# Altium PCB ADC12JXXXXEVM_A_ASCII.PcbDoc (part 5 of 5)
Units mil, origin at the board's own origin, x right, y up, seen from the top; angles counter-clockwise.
Board outline 5739 x 2680 mil, 10 copper layers (Top Layer L1, Gnd-Plane - L2, Signals - L3, Gnd-Plane - L4, Pwr Plane - L5, Signals - L6, Gnd-Plane - L7, Signals - L8, Gnd-Plane - L9, Bottom Layer - L10), stack 57.8 mil thick; 582 components, 343 nets, 1924 pads, 1318 vias.
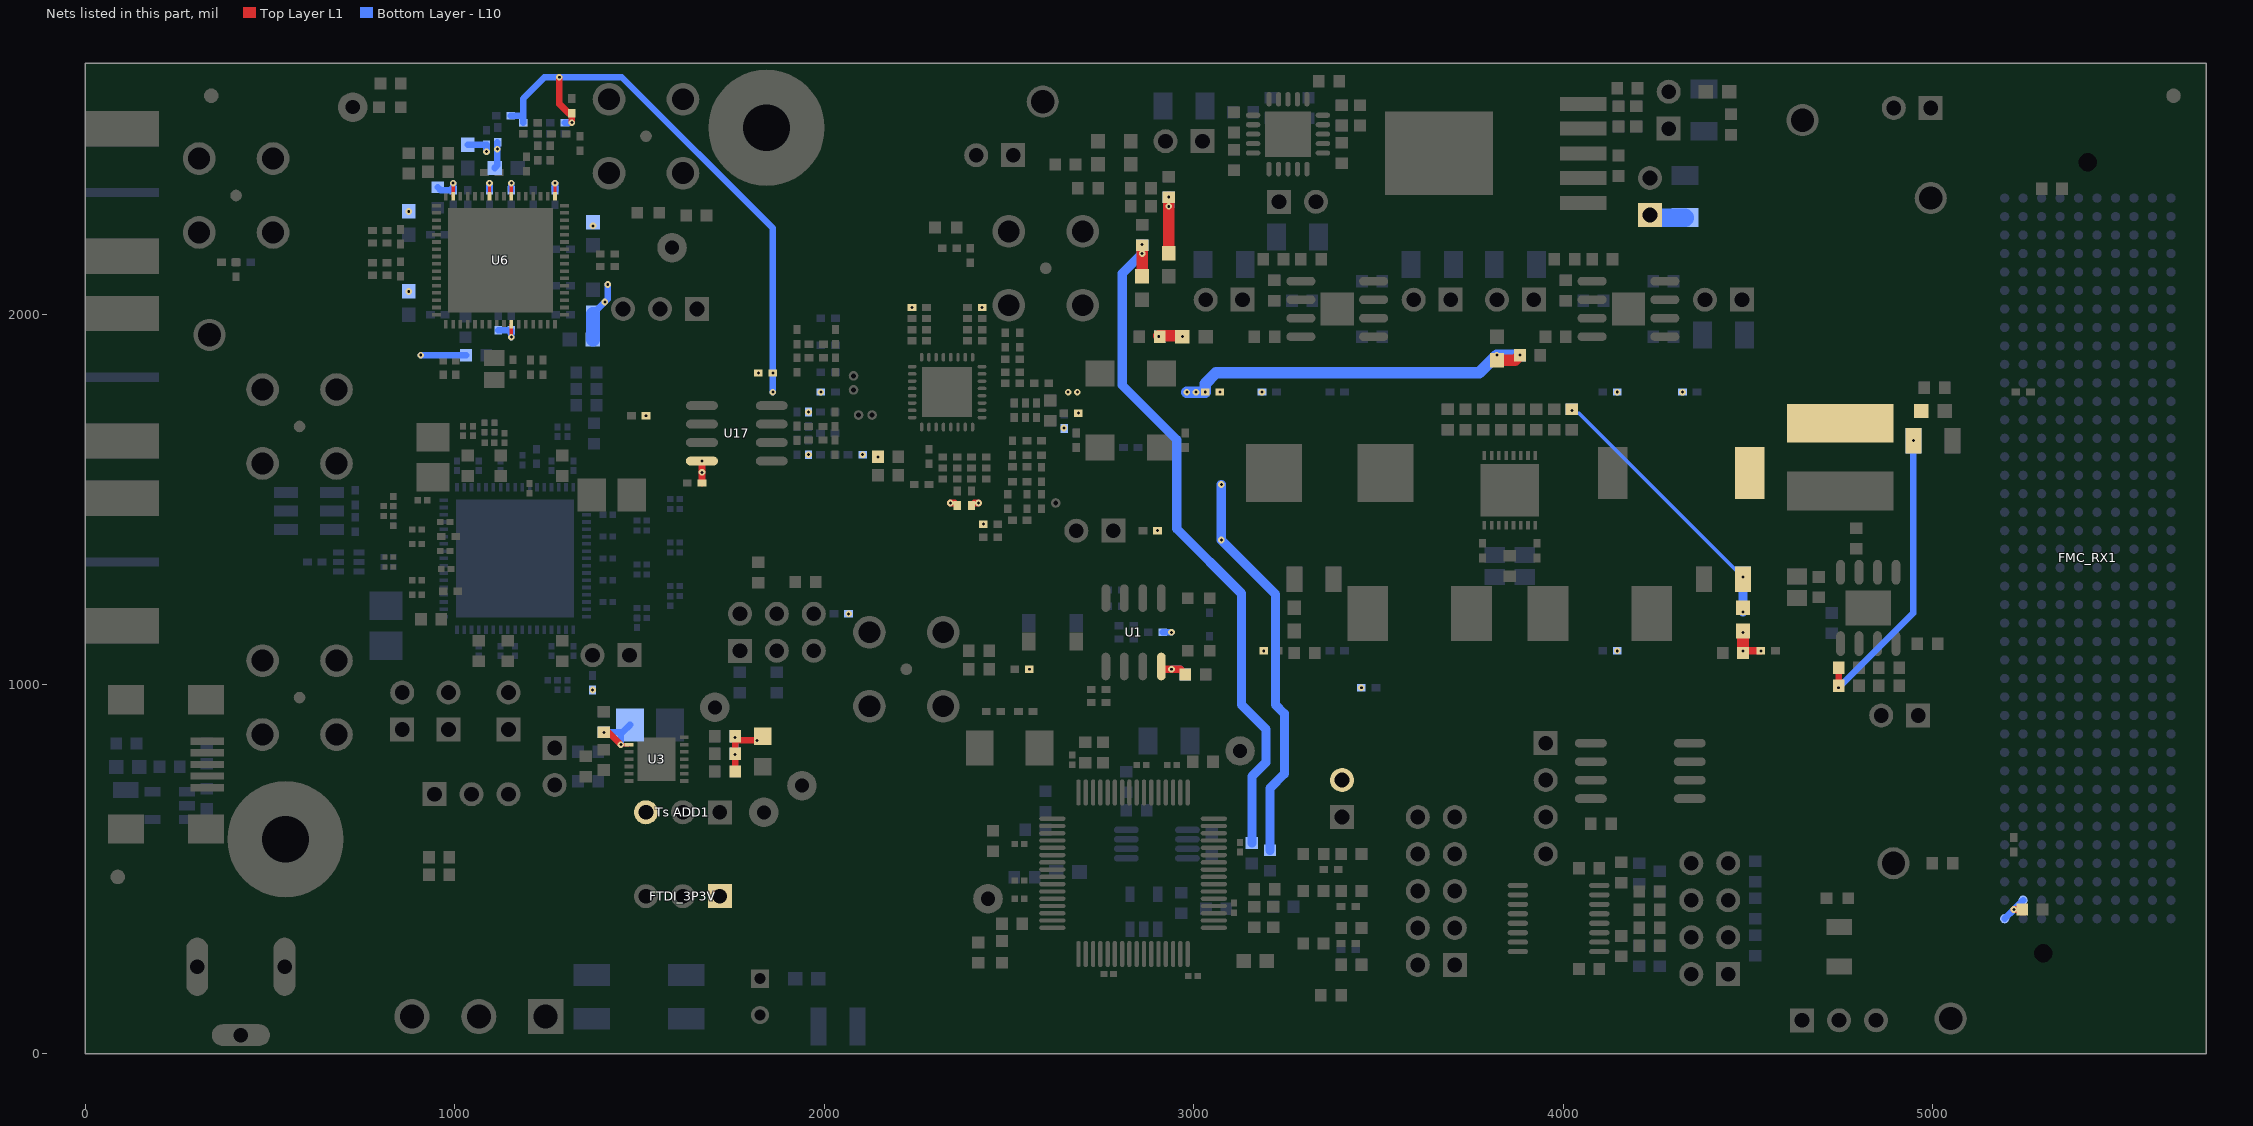
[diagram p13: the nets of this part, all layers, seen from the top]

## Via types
v1: diameter 18, hole 8, Top Layer L1 to Bottom Layer - L10, tented both sides, 1098 vias
v2: diameter 19.68, hole 7.87, Top Layer L1 to Bottom Layer - L10, 99 vias
v3: diameter 18, hole 8, Top Layer L1 to Bottom Layer - L10, tented bottom, 58 vias
v4: diameter 18, hole 8, Top Layer L1 to Bottom Layer - L10, tented top, 48 vias
v5: diameter 25.98, hole 12.99, Top Layer L1 to Bottom Layer - L10, tented top, 8 vias
v6: diameter 19.68, hole 7.87, Top Layer L1 to Bottom Layer - L10, tented top, 5 vias
v7: diameter 126, hole 106, Top Layer L1 to Bottom Layer - L10, tented top, 2 vias

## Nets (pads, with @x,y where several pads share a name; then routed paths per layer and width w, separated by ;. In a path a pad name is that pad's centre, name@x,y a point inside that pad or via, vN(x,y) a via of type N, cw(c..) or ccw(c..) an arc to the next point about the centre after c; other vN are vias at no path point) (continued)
VIO_2P25: 1V9INT.1 C199.1 C203.1 C222.1 C223.1 C226.1 C227.1 L20.2 R95.1 | length 258.5
  Top Layer L1 w19.5: v1(4486.15,1090) v1(4534.31,1090)
  Top Layer L1 w31.5: v1(4486.15,1090) L20.2@4486.15,1143.5
  Bottom Layer - L10 w24: C203.1@4486.15,1084 v1@4486.15,1143.5
  Bottom Layer - L10 w51: 1V9INT.1@4234,2269.07 4241.09,2261.98 R95.1@4328.44,2261.98
  other v1: 4145.69,1090 4486.15,1140 4145.69,1790 4322.32,1790
VIO_2P25V: C174.2 C180.1 C181.1 L11.1 L20.1 R81.1 | length 745.3
  Bottom Layer - L10 w10: R81.1@4023,1743.56 4033.56,1733 4042,1733 4470,1305 4470,1299.15 C181.1@4486.15,1283
  Bottom Layer - L10 w24: v1@4486.15,1195 C181.1@4486.15,1283
  other v1: 4486.15,1195 4486.15,1290 4023,1740
VIO_3P3V: "Ts ADD1.3" C24.1 C25.1 C27.1 C95.1 C96.1 C115.1 C125.1 C153.1 C163.1 C215.1 C216.1 C217.1 C218.1 C219.2 C220.1 C224.2 FTDI_3P3V.1 J3.2 L9.2 R1.2 R14.2 R15.2 R16.2 R31.2 R32.2 TEMP.1 U1.8 U3.2 | length 651.2
  Top Layer L1 w9: v1(1449.28,836.13) U3.2@1471.47,836.13
  Top Layer L1 w18: v1(1403.28,869.44) 1415.96,869.44 v1(1449.28,836.13) ; R16.2@1758.84,763.41 v1(1758.84,809.41) 1758.84,847.47 v1(1818.28,847.47)
  Top Layer L1 w19.5: U1.8@2912,1040 2962.93,1040 C125.1@2976.93,1026
  Top Layer L1 w30: C153.1@2905,1942.56 2966.45,1942.56 v1(2969.01,1940)
  Bottom Layer - L10 w18: v1(1403.28,869.44) 1454.17,869.44 C27.1@1474.14,889.42 ; v1(1449.28,836.13) C27.1@1449.3,869.44 ; v1(1758.84,809.41) v1(1758.84,855.81) ; v1(2905,1940) v1(2969.01,1940) ; R1.2@2915.69,1140 v1(2939.5,1140)
  Bottom Layer - L10 w19.5: v1(2939.5,1040) 2962.93,1040 C115.1@2976.93,1026
  other v1: 1373,983.82 3453.31,990 2554.68,1040 3189.16,1090 2065.68,1190 1517.68,1726 3070.24,1790 3184.31,1790 1821.32,1842
VIO_3P3V_LMK_CLK: C116.1 C171.1 L2.1 L4.1 L13.2 L19.1 L21.1 L22.1 R47.2 R131.1 | length 2191.3
  Top Layer L1 w31.5: L13.2@2860,2102.99 C116.1@2860,2187.44
  Bottom Layer - L10 w18: v1(908,1890) R47.2@1030.23,1890 ; L4.1@1373.92,2001.92 v1(1406,2034) 1414,2042 v1(1414,2081)
  Bottom Layer - L10 w25: v1(2860,2165) 2806,2111 2806,1809 2954,1661 2954,1420 3129,1245 3129,944 3195,878 3195,788 3157,750 R131.1@3157,569.71
  Bottom Layer - L10 w31.5: v1@2860,2162.44 C171.1@2860,2187.44
  Bottom Layer - L10 w37.5: L2.1@1373.92,1932.5 L4.1@1373.92,2001.92
  other v1: 875.5,2062.35 2860,2190 1373.92,2240 875.5,2278.89
VIO_3P3V_LMK_PLL: C102.1 C104.1 C107.1 C108.1 C109.1 C164.1 C165.1 C206.1 C207.1 C208.1 C209.1 L3.1 L5.1 L10.2 U6.10 U6.33 U6.39 U6.42 U6.47 | length 669.2
  Top Layer L1 w9: U6.47@995.61,2320.23 v1(995.61,2355.31) ; U6.42@1094.03,2320.23 v1(1094.03,2355.31) ; v1(1153.09,1938.69) U6.10@1153.09,1973.77 ; U6.39@1153.09,2320.23 v1(1153.09,2355.31) ; U6.33@1271.2,2320.23 v1(1271.2,2355.31)
  Top Layer L1 w31.5: L10.2@2932,2165.99 v1(2932,2317.5)
  Bottom Layer - L10 w18: C108.1@953.92,2344.32 961.79,2336.44 C209.1@995.61,2336.45 v1(995.61,2355.31) ; L5.1@1034.98,2459.5 C107.1@1085.92,2459.5 v1(1085.92,2440.63) ; C208.1@1094.03,2336.45 v1(1094.03,2355.31) ; L3.1@1107.96,2396.5 1115.05,2403.59 v1(1115.05,2447.5) C104.1@1115.05,2466.37 ; C109.1@1117.72,1957.55 C102.1@1153.09,1957.55 v1(1153.09,1938.69) ; C207.1@1153.09,2336.45 v1(1153.09,2355.31) ; C206.1@1271.2,2336.45 v1(1271.2,2355.31)
  Bottom Layer - L10 w31.5: v1(2932,2292.5) v1(2932,2317.5)
VIO_3P3V_LMX: C144.1 C152.1 C216.2 C217.2 C258.2 C259.2 C260.2 L1.1 L6.2 L27.1 L28.1 L29.1 L30.1 L31.1 L32.1 L33.1 L34.1 R130.1 R146.1 R151.1 R156.2 R157.2 R163.2 R164.2 U17.8 | length 3776.2
  Top Layer L1 w18: v1(1283,2642) 1283,2569.78 1307.91,2544.87 C259.2@1316.91,2544.87 v1(1316.91,2519) ; C258.2@1668.84,1544.09 v1(1668.84,1603.5) ; v1(2341.08,1490) 2352.92,1490 L30.1@2359.92,1483 ; L29.1@2398.55,1483 2405.55,1490 v1(2417.39,1490)
  Top Layer L1 w31.5: L6.2@3820,1876.5 3868.94,1876.5 v1(3882.44,1890)
  Bottom Layer - L10 w18: C260.2@1151.69,2537.87 1185.3,2537.87 ; R157.2@1185.3,2519 1185.3,2537.87 ; R156.2@1298.04,2519 v1(1316.91,2519) ; v1(1860.69,1790) 1860.69,2233.31 1452,2642 1243,2642 1185.3,2584.3 1185.3,2537.87
  Bottom Layer - L10 w25: v1(3074.2,1540) v1(3074.2,1390) 3221,1243.2 3221,944 3245,920 3245,757 3206,718 R130.1@3206,550.02
  Bottom Layer - L10 w31.5: v1(2980.87,1790) v1(3030.87,1790) 3030.87,1812.87 3060,1842 3772,1842 v1(3820,1890) v1(3882.44,1890)
  other v1: 2901.68,1415 2430.31,1432.5 1668.84,1572.81 2145.44,1615 1957.36,1620.81 2103.69,1620.82 2648,1692.98 2687.52,1733.13 1957.36,1736.19 1990.68,1790 2659.92,1790 2684.92,1790 3005.87,1790 1860.69,1842 2237.35,2019.09 2427.12,2019.09
VIO_3P6V: C154.2 C156.2 C157.2 L7.1 L8.2 R72.1 | length 801.4
  Top Layer L1 w18: R72.1@4744.88,995 C154.2@4744.88,1044
  Bottom Layer - L10 w18: v1(4744.88,990) 4946.85,1191.97 v1(4946.85,1658.75)
VIO_B_M2C_RX: FMC_RX1.J39 FMC_RX1.K40 RR7.2 | length 93.2
  Top Layer L1 w18: v1(5219,390) RR7.2@5241.44,390
  Bottom Layer - L10 w18: FMC_RX1.K40@5194,365 v1(5219,390) FMC_RX1.J39@5244,415
pads on no net: 5VDC.3 "SH-Ts ADD1_1_2.0" FID1.1 FID2.1 FID3.1 FMC_RX1.401 FMC_RX1.402 FMC_RX1.A22 FMC_RX1.A23 FMC_RX1.A26 FMC_RX1.A27 FMC_RX1.A30 FMC_RX1.A31 FMC_RX1.A34 FMC_RX1.A35 FMC_RX1.A38 FMC_RX1.A39 FMC_RX1.B1 FMC_RX1.B4 FMC_RX1.B5 FMC_RX1.B8 FMC_RX1.B9 FMC_RX1.B20 FMC_RX1.B21 FMC_RX1.B24 FMC_RX1.B25 FMC_RX1.B28 FMC_RX1.B29 FMC_RX1.B32 FMC_RX1.B33 FMC_RX1.B36 FMC_RX1.B37 FMC_RX1.B40 FMC_RX1.C2 FMC_RX1.C3 FMC_RX1.C10 FMC_RX1.C11 FMC_RX1.C14 FMC_RX1.C15 FMC_RX1.C18 FMC_RX1.C19 FMC_RX1.C22 FMC_RX1.C23 FMC_RX1.C26 FMC_RX1.C27 FMC_RX1.D8 FMC_RX1.D9 FMC_RX1.D11 FMC_RX1.D12 FMC_RX1.D14 FMC_RX1.D15 FMC_RX1.D17 FMC_RX1.D18 FMC_RX1.D20 FMC_RX1.D21 FMC_RX1.D23 FMC_RX1.D24 FMC_RX1.D27 FMC_RX1.D29 FMC_RX1.D33 FMC_RX1.D34 FMC_RX1.E2 FMC_RX1.E3 FMC_RX1.E6 FMC_RX1.E7 FMC_RX1.E9 FMC_RX1.E10 FMC_RX1.E15 FMC_RX1.E16 FMC_RX1.E18 FMC_RX1.E19 FMC_RX1.E21 FMC_RX1.E22 FMC_RX1.E24 FMC_RX1.E25 FMC_RX1.E27 FMC_RX1.E28 FMC_RX1.E30 FMC_RX1.E31 FMC_RX1.E33 FMC_RX1.E34 FMC_RX1.E37 FMC_RX1.F4 FMC_RX1.F5 FMC_RX1.F7 FMC_RX1.F8 FMC_RX1.F10 FMC_RX1.F11 FMC_RX1.F13 FMC_RX1.F14 FMC_RX1.F16 FMC_RX1.F17 FMC_RX1.F19 FMC_RX1.F20 FMC_RX1.F22 FMC_RX1.F23 FMC_RX1.F25 FMC_RX1.F26 FMC_RX1.F28 FMC_RX1.F29 FMC_RX1.F31 FMC_RX1.F32 FMC_RX1.F34 FMC_RX1.F35 FMC_RX1.F37 FMC_RX1.F38 FMC_RX1.G2 FMC_RX1.G3 FMC_RX1.G15 FMC_RX1.G16 FMC_RX1.G18 FMC_RX1.G19 FMC_RX1.G21 FMC_RX1.G22 FMC_RX1.G24 FMC_RX1.G25 FMC_RX1.G28 FMC_RX1.G31 FMC_RX1.H1 FMC_RX1.H4 FMC_RX1.H5 FMC_RX1.H7 FMC_RX1.H8 FMC_RX1.H10 FMC_RX1.H11 FMC_RX1.H13 FMC_RX1.H14 FMC_RX1.H16 FMC_RX1.H17 FMC_RX1.H19 FMC_RX1.H20 FMC_RX1.H22 FMC_RX1.H23 FMC_RX1.H25 FMC_RX1.H26 FMC_RX1.H28 FMC_RX1.H29 FMC_RX1.H32 FMC_RX1.H35 FMC_RX1.J2 FMC_RX1.J3 FMC_RX1.J6 FMC_RX1.J7 FMC_RX1.J9 FMC_RX1.J10 FMC_RX1.J12 FMC_RX1.J13 FMC_RX1.J18 FMC_RX1.J19 FMC_RX1.J21 FMC_RX1.J22 FMC_RX1.J24 FMC_RX1.J25 FMC_RX1.J27 FMC_RX1.J28 FMC_RX1.J30 FMC_RX1.J31 FMC_RX1.J33 FMC_RX1.J34 FMC_RX1.J36 FMC_RX1.J37 FMC_RX1.K1 FMC_RX1.K4 FMC_RX1.K5 FMC_RX1.K7 FMC_RX1.K8 FMC_RX1.K10 FMC_RX1.K11 FMC_RX1.K13 FMC_RX1.K14 FMC_RX1.K16 FMC_RX1.K17 FMC_RX1.K19 FMC_RX1.K20 FMC_RX1.K22 FMC_RX1.K23 FMC_RX1.K25 FMC_RX1.K26 FMC_RX1.K31 FMC_RX1.K32 FMC_RX1.K34 FMC_RX1.K35 H3.0 H4.0 H5.1 H6.1 S1.3 SH-1V2ADC_INT_1_2.0 SH-1V2ADC_LDO_1_2.0 SH-1V9ADC_1_2.0 SH-1V9INT_1_2.0 SH-5V_12V_1_2.0 SH-FTDI_3P3V_1_2.0 SH-J2_1_2.0 SH-LMK_INT_1_2.0 SH-LMK_LDO_1_2.0 SH-LMX_INT_1_2.0 SH-LMX_LDO_1_2.0 SH-RSV_1_2.0 U3.1 U3.3 U3.4 U5.2 U5.7 U8.2 U8.7 U10.2 U10.3 U10.4 U10.9 U10.13 U10.14 U10.17 U13.21 U13.22 U13.23 U13.24 U13.30 U13.32 U13.33 U13.34 U13.36 U13.44 U13.45 U13.46 U13.48 U13.52 U13.53 U13.54 U13.55 U13.57 U13.58 U13.59 U13.60 U15.6 U15.7 U16.7 U17.4 USB.4 uWIRE.1 uWIRE.3 uWIRE.5 uWIRE.7
copper on no net:
  other v7: 5340,100 5340,2580

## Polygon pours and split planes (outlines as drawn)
GND on Top Layer L1 "Top Layer L1-U9 GND" (solid, pour order 33): 4050,1819 3107,1819 3107,1111 3243,1111 3243,1177 3131,1177 3131,1660 3303,1660 3303,1111 3353,1111 3353,1032 4024,1032 4024,1105 3890,1105 3890,1307.54 3820,1307.54 3820,1105 3686,1105 3686,1266 3432,1266 3432,1660 3625,1660 3626,1363 3761,1363 3761,1453 3949,1453 3949,1363 4084,1363 4084,1660 4278,1660 4278,1266 4024,1266 4024,1032 4405,1032 4405,1110 4455,1110 4455,1660 4554,1660 4554,1176 4515,1176 4515,1110 4578,1110 4579,1782 4948,1782 4948,1819 4050,1819 4050,1663 3970,1663 3949,1642 3949,1596 3761,1596 3761,1642 3740,1663 3660,1663 3660,1769 3718,1769 3718,1728 3848,1728 3848,1769 3910,1769 3910,1728 3992,1728 3992,1769 4050,1769
GND on Top Layer L1 "Top Layer L1-U2-GND" (solid, pour order 41): 995,1182 995,1303 980,1303 980,1368 991,1368 991,1430 978,1430 978,1447 995,1447 995,1526 1322,1526 1322,1182
Net1V2ADC_INT_2 on Top Layer L1 "Top Layer L1-NetC172_1" (solid, pour order 44): 3329.68,2488 3329.68,2413 3299,2413 3299,2272 3369,2272 3369,2393 3418,2393 3418,2425 3368.68,2425 3368.68,2488
Net1V2ADC_LDO_1 on Top Layer L1 "Top Layer L1-NetC172_1" (solid, pour order 43): 3179.68,2495 3179.68,2413 3203.68,2413 3203.68,2374 3140.68,2374 3140.68,2430 2990.68,2430 2990.68,2508 3125.68,2508 3125.68,2495
VIO_1P9V on Top Layer L1 "Top Layer L1-VIO_1P9V" (solid, remove dead copper, pour order 45): 973,1301 953,1301 953,1297 947,1291 940,1291 934,1297 934,1363 940,1369 970,1369 970,1320 973,1320
5P0_12P0V_INT on Top Layer L1 "Top Layer L1-12P0_INT" (solid, pour order 36): 3890,1405 3820,1405 3820,1331 3890,1331 3890,1405
VIO_3P6V on Top Layer L1 "Top Layer L1-VIO_3P6V" (solid, pour order 56): 4969,1624 4969,1720 4988,1720 4988,1758 4605,1758 4605,1653 4910,1653 4910,1624
5P0_12P0V_INT on Top Layer L1 "Top Layer L1-U7-12V_int" (solid, pour order 55): 4762,1269 4762,1336 4604,1336 4604,1269
GND on Top Layer L1 "Top Layer L1-U7-SW_GND" (solid, pour order 51): 4762,1346 4762,1453 4604,1453 4604,1346
NetC168_1 on Top Layer L1 "Top Layer L1-NetC168_1" (solid, pour order 34): 3890,1643 3820,1643 3820,1704 3890,1704 3890,1643
NetC170_1 on Top Layer L1 "Top Layer L1-NetC170_1" (solid, pour order 58): 3811,1442 3800,1442 3800,1405 3796,1405 3796,1353 3616,1353 3616,1650 3442,1650 3442,1276 3696,1276 3696,1115 3811,1115
NetC169_2 on Top Layer L1 "Top Layer L1-NetC169_2" (solid, pour order 57): 3899,1442 3910,1442 3910,1405 3914,1405 3914,1353 4094,1353 4094,1650 4268,1650 4268,1276 4014,1276 4014,1115 3899,1115
VIO_1P4V on Top Layer L1 "Top Layer L1- VIO_1P4V" (solid, pour order 62): 3293,1650 3141,1650 3141,1186 3293,1186 3293,1650
VIO_2P25V on Top Layer L1 "Top Layer L1- VIO_1P4V" (solid, pour order 61): 4465,1650 4544,1650 4544,1186 4465,1186 4465,1650
GND on Top Layer L1 "Top Layer L1-U7-GND" (solid, pour order 50): 5075,1158 5075,1694 5031,1694 5031,1614 4910,1614 4910,1336 4888,1336 4888,1254 4604,1254 4604,1158 4996,1158 4996,1092 5029,1092 5029,1158
GND on Bottom Layer - L10 "Top Layer L10-GND" (solid, pour order 52): 2263.34,1858.9 2263.34,1721.1 2401.13,1721.1 2401.13,1858.9
GND on Bottom Layer - L10 "Top Layer L10-GND" (solid, pour order 53): 1886,2000 1886,1834 2003,1834 2003,2000
GND on Bottom Layer - L10 "Bottom Layer - L10-T2-GND" (solid, pour order 38): 403,1364 620,1364 620,1453 701,1453 701,1483 620,1483 620,1572 403,1572
5P0_12P0V_INT on Bottom Layer - L10 "Top Layer L10-12P0_INT" (solid, pour order 35): 3890,1405 3820,1405 3820,1327 3890,1327 3890,1405
GND on Bottom Layer - L10 "Bottom Layer - L10-U6-GND" (solid, pour order 39): 961,1989 1012,1989 1012,1978 1046,1978 1046,1985 1286,1985 1286,2310 985,2310 985,2305 937,2305 937,2273 961,2273
GND on Bottom Layer - L10 "Bottom Layer - L10-U10-GND" (solid, pour order 37): 3191,2426 3327,2426 3327,2550 3191,2550 3176,2565 3144,2565 3144,2530 3191,2483
VIO_3P3V_LMX on Signals - L3 "Bottom Layer L10 - VIO_3P3V_LMX" (solid, remove dead copper, pour order 59): 1848,2043 2261,2043 2261,1954 1977,1954 1977,1777 1848,1777
VIO_3P3V_LMX on Signals - L3 "Bottom Layer L10 - VIO_3P3V_LMX" (solid, remove dead copper, pour order 60): 2698,2043 2403,2043 2403,1954 2457,1954 2457,1777 2698,1777
1P8V_USB on Signals - L3 "Signals - L3-1P8V_USB" (solid, pour order 49): 2550,387 2550,441 2639,441 2639,773 2703,773 2703,729 2976,729 2976,783 3015,783 3015,550 2703,550 2703,441 3143,441 3143,387
3P3V_USB on Signals - L3 "Signals - L3-3P3V_USB" (solid, remove dead copper, pour order 46): 20.1,1029.9 400.9,1029.9 400.9,843.1 436,808 641,808 877,572 1550,572 1550,393 1485,393 1485,443 902,443 609,736 493,736 401,644 400.9,535.1 20.1,535.1
3P3V_FTDI on Signals - L3 "Signals - L3-3P3V_FTDI" (solid, pour order 47): 1584,572 2358,572 2358,970 2645,970 2645,888 3117.89,887.9 3244.9,760.89 3245,476 3153,476 3153,451 2713,451 2713,540 3025,540 3025,793 2966,793 2966,739 2713,739 2713,783 2629,783 2629,451 2540,451 2540,377 3153,377 3153,476 3245,476 3245,389 3160,304 3159.9,167.11 3072.89,80.1 2683.11,80.1 2560,203 2419.21,203 2358.1,264.11 2358.1,443 1650,443 1650,393 1584,393
VIO_1P9V on Signals - L3 "Signals - L3-VIO_1P9V" (solid, pour order 40): 897,2660 4460,2660 4460,2094 2772,2094 2772,2285 2439,2285 2439,2094 1119,2094 1119,1592 1196,1592 1196,944 1095,944 1095,1046 769,1046 769,1142 897,1142
VIO_3P3V_LMK_CLK on Signals - L8 "Signals - L8-VIO_3P3V_LMK_CLK" (solid, pour order 48): 1521,2153 3091,2153 3091,2661 831,2660 831,1871 936,1871 936,2522 1311,2522 1311,2378 2991,2378 2991,2252 1310,2252 1310,2025 1423,2025 1423,2097 1400,2097 1400,2197 1477,2197
VIO_3P3V_LMK_PLL on Signals - L8 "Signals - L8-VIO_3P3V_LMK_PLL" (solid, pour order 42): 1108,1924 1168,1924 1168,1995 1203,2030 1286,2030 1286,2277 2966,2277 2966,2353 1286,2353 1286,2497 961,2497 961,1974 1108,1974
no net on Top Overlay "Top Overlay-No Net" (solid): 5594,139 5594,39 5694,39 5694,139 5594,139
no net on Top Overlay "Top Overlay-No Net" (solid): 5444,139 5444,39 5544,39 5544,139 5444,139
no net on Top Overlay "Top Overlay-No Net" (solid): 5446,1010 5446,910 5546,910 5546,1010 5446,1010
no net on Top Overlay "Top Overlay-No Net" (solid): 5592,1009 5592,909 5692,909 5692,1009 5592,1009
GND2 on Gnd-Plane - L2 (split plane): 400.9,845 401.29,843.05 402.4,841.4 434.4,809.4 436.05,808.29 438,807.9 641.52,807.9 875.65,573.77 877.31,572.66 879.26,572.27 2353,572.27 2354.95,572.66 2356.6,573.77 2357.71,575.42 2358.1,577.37 2358.1,969.9 2644.9,969.9 2644.9,893 2645.29,891.05 2646.4,889.4 2648.05,888.29 2650,887.9 3117.89,887.9 3244.9,760.89 3244.9,389.11 3161.4,305.6 3160.29,303.95 3159.9,302 3159.9,167.11 3072.89,80.1 2683.11,80.1 2561.6,201.6 2559.95,202.71 2558,203.1 2419.11,203.1 2358.1,264.11 2358.1,438 2357.71,439.95 2356.6,441.6 2354.95,442.71 2353,443.1 902.11,443.1 610.6,734.6 608.95,735.71 607,736.1 495,736.1 493.05,735.71 491.4,734.6 402.4,645.6 401.29,643.95 400.9,642 400.9,535.1 20.1,535.1 20.1,1029.9 400.9,1029.9
GND on Gnd-Plane - L2 (split plane): 5718.9,20.1 20.1,20.1 20.1,524.9 406,524.9 407.95,525.29 409.6,526.4 410.71,528.05 411.1,530 411.1,639.89 497.11,725.9 604.89,725.9 896.39,434.4 898.05,433.29 900,432.9 2347.9,432.9 2347.9,262 2348.29,260.05 2349.4,258.4 2413.4,194.4 2415.05,193.29 2417,192.9 2555.89,192.9 2677.4,71.4 2679.05,70.29 2681,69.9 3075,69.9 3076.95,70.29 3078.6,71.4 3168.6,161.4 3169.71,163.05 3170.1,165 3170.1,299.89 3253.6,383.4 3254.71,385.05 3255.1,387 3255.1,763 3254.71,764.95 3253.6,766.6 3123.6,896.6 3121.95,897.71 3120,898.1 2655.1,898.1 2655.1,975 2654.71,976.95 2653.6,978.6 2651.95,979.71 2650,980.1 2353,980.1 2351.05,979.71 2349.4,978.6 2348.29,976.95 2347.9,975 2347.9,582.47 881.37,582.47 647.23,816.6 645.58,817.71 643.63,818.1 440.11,818.1 411.1,847.11 411.1,1035 410.71,1036.95 409.6,1038.6 407.95,1039.71 406,1040.1 20.1,1040.1 20.1,2659.9 5718.9,2659.9
GND on Gnd-Plane - L4 (split plane): 5718.9,20.1 20.1,20.1 20.1,2659.9 5718.9,2659.9
NetC158_1 on Pwr Plane - L5 (split plane): 5718.9,1995.1 4347.1,1995.1 4347.1,2419 4346.71,2420.95 4345.6,2422.6 4343.95,2423.71 4342,2424.1 4126,2424.1 4124.05,2423.71 4122.4,2422.6 4121.29,2420.95 4120.9,2419 4120.9,1995.1 3650.1,1995.1 3650.1,2659.9 5718.9,2659.9
VIO_2P25 on Pwr Plane - L5 (split plane): 4336.9,1184 4337.29,1182.05 4338.4,1180.4 4340.05,1179.29 4342,1178.9 4548.9,1178.9 4548.9,1045.1 4131.1,1045.1 4131.1,2413.9 4336.9,2413.9
VIO_1P4 on Pwr Plane - L5 (split plane): 3382.9,1045.1 3209.1,1045.1 3209.1,1990 3208.71,1991.95 3207.6,1993.6 3205.95,1994.71 3204,1995.1 2976.1,1995.1 2976.1,2659.9 3382.9,2659.9
5P0_12P0V_INT on Pwr Plane - L5 (split plane): 3639.9,1990 3640.29,1988.05 3641.4,1986.4 3643.05,1985.29 3645,1984.9 4120.9,1984.9 4120.9,1040 4121.29,1038.05 4122.4,1036.4 4124.05,1035.29 4126,1034.9 4554,1034.9 4555.95,1035.29 4557.6,1036.4 4558.71,1038.05 4559.1,1040 4559.1,1184 4558.71,1185.95 4557.6,1187.6 4555.95,1188.71 4554,1189.1 4347.1,1189.1 4347.1,1984.9 5718.9,1984.9 5718.9,670.1 5544,670.1 5542.05,669.71 5540.4,668.6 5539.29,666.95 5538.9,665 5538.9,570.1 4796,570.1 4794.05,569.71 4792.4,568.6 4791.29,566.95 4790.9,565 4790.9,20.1 4701.1,20.1 4701.1,190 4700.71,191.95 4699.6,193.6 4697.95,194.71 4696,195.1 3478.1,195.1 3478.1,1040 3477.71,1041.95 3476.6,1043.6 3474.95,1044.71 3473,1045.1 3393.1,1045.1 3393.1,2659.9 3639.9,2659.9
12P0V_RX on Pwr Plane - L5 (split plane): 5718.9,20.1 4801.1,20.1 4801.1,559.9 5544,559.9 5545.95,560.29 5547.6,561.4 5548.71,563.05 5549.1,565 5549.1,659.9 5718.9,659.9
VIO_1P2VD on Pwr Plane - L5 (split plane): 2965.9,1995.1 2871,1995.1 2869.05,1994.71 2867.4,1993.6 2866.29,1991.95 2865.9,1990 2865.9,1945.1 2452,1945.1 2450.05,1944.71 2448.4,1943.6 2424.89,1920.1 1435,1920.1 1433.05,1919.71 1431.4,1918.6 1401.4,1888.6 1400.29,1886.95 1399.9,1885 1399.9,1710 1400.29,1708.05 1401.4,1706.4 1434.9,1672.89 1434.9,1245 1435.29,1243.05 1436.4,1241.4 1438.05,1240.29 1440,1239.9 2003.9,1239.9 2003.9,1040.1 1200,1040.1 1198.05,1039.71 1196.4,1038.6 1195.29,1036.95 1194.9,1035 1194.9,657.1 1095.1,657.1 1095.1,1779.89 1094.71,1781.84 1093.6,1783.5 1030.1,1847.01 1030.1,1988.85 1117.15,2075.9 2785,2075.9 2786.95,2076.29 2788.6,2077.4 2789.71,2079.05 2790.1,2081 2790.1,2659.9 2965.9,2659.9
VIO_3P3V_LMX on Pwr Plane - L5 (split plane): 1916.9,1840 1917.29,1838.05 1918.4,1836.4 1920.05,1835.29 1922,1834.9 3045.45,1834.9 3045.45,1740 3045.84,1738.05 3046.95,1736.4 3048.6,1735.29 3050.55,1734.9 3088.45,1734.9 3088.45,1468.1 2941,1468.1 2939.05,1467.71 2937.4,1466.6 2936.29,1464.95 2935.9,1463 2935.9,1381.1 2867.1,1381.1 2867.1,1415 2866.71,1416.95 2865.6,1418.6 2863.95,1419.71 2862,1420.1 2380.11,1420.1 2283.6,1516.6 2281.95,1517.71 2280,1518.1 1720.1,1518.1 1720.1,1558 1719.71,1559.95 1718.6,1561.6 1716.95,1562.71 1715,1563.1 1660.1,1563.1 1660.1,1707.17 1841,1707.17 1842.95,1707.56 1844.6,1708.67 1845.71,1710.32 1846.1,1712.27 1846.1,1859.9 1916.9,1859.9
VIO_1P2VA on Pwr Plane - L5 (split plane): 2779.9,2086.1 1115.04,2086.1 1113.09,2085.71 1111.43,2084.6 1021.4,1994.57 1020.29,1992.91 1019.9,1990.96 1019.9,1844.89 1020.29,1842.94 1021.4,1841.29 1084.9,1777.78 1084.9,1040.1 20.1,1040.1 20.1,2659.9 2779.9,2659.9
NetC194_1 on Pwr Plane - L5 (split plane): 400.9,845 401.29,843.05 402.4,841.4 434.4,809.4 436.05,808.29 438,807.9 641.52,807.9 875.65,573.77 877.31,572.66 879.26,572.27 1662.18,572.27 1662.18,376 1662.57,374.05 1663.67,372.4 1665.33,371.29 1667.28,370.9 1767.28,370.9 1769.23,371.29 1770.88,372.4 1771.99,374.05 1772.37,376 1772.37,572.27 2018,572.27 2019.95,572.66 2021.6,573.77 2022.71,575.42 2023.1,577.37 2023.1,969.9 2644.9,969.9 2644.9,893 2645.29,891.05 2646.4,889.4 2648.05,888.29 2650,887.9 3117.89,887.9 3244.9,760.89 3244.9,190 3245.29,188.05 3246.4,186.4 3248.05,185.29 3250,184.9 4690.9,184.9 4690.9,20.1 20.1,20.1 20.1,1029.9 400.9,1029.9
VIO_3P3V on Pwr Plane - L5 (split plane): 3198.9,1040 3199.29,1038.05 3200.4,1036.4 3202.05,1035.29 3204,1034.9 3467.9,1034.9 3467.9,195.1 3255.1,195.1 3255.1,763 3254.71,764.95 3253.6,766.6 3123.6,896.6 3121.95,897.71 3120,898.1 2655.1,898.1 2655.1,975 2654.71,976.95 2653.6,978.6 2651.95,979.71 2650,980.1 2018,980.1 2016.05,979.71 2014.4,978.6 2013.29,976.95 2012.9,975 2012.9,582.47 1767.28,582.47 1765.33,582.08 1763.67,580.98 1762.57,579.32 1762.18,577.37 1762.18,381.1 1672.37,381.1 1672.37,577.37 1671.99,579.32 1670.88,580.98 1669.23,582.08 1667.28,582.47 1667.27,582.47 881.37,582.47 647.23,816.6 645.58,817.71 643.63,818.1 440.11,818.1 411.1,847.11 411.1,1029.9 1084.9,1029.9 1084.9,652 1085.29,650.05 1086.4,648.4 1088.05,647.29 1090,646.9 1200,646.9 1201.95,647.29 1203.6,648.4 1204.71,650.05 1205.1,652 1205.1,1029.9 2009,1029.9 2010.95,1030.29 2012.6,1031.4 2013.71,1033.05 2014.1,1035 2014.1,1245 2013.71,1246.95 2012.6,1248.6 2010.95,1249.71 2009,1250.1 1445.1,1250.1 1445.1,1675 1444.71,1676.95 1443.6,1678.6 1410.1,1712.11 1410.1,1882.89 1437.11,1909.9 2427,1909.9 2428.95,1910.29 2430.6,1911.4 2454.11,1934.9 2871,1934.9 2872.95,1935.29 2874.6,1936.4 2875.71,1938.05 2876.1,1940 2876.1,1984.9 3198.9,1984.9
GND on Gnd-Plane - L7 (split plane): 5718.9,20.1 20.1,20.1 20.1,2659.9 5718.9,2659.9
GND on Gnd-Plane - L9 (split plane): 5718.9,20.1 20.1,20.1 20.1,2659.9 5718.9,2659.9

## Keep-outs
Keep-Out Layer:
  text ".Layer_Name" at 577,-858.49 h60

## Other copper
Top Layer L1:
  text ".CopyrightYear" at 4709,2073 h60
  text "TI" at 4985,2073 h60
  text "©" at 4592,2069.48 h105
  text ".Layer_Name" at 577,-858.49 h60
Signals - L3:
  text ".Layer_Name" at 577,-858.49 h60
Signals - L6:
  text ".Layer_Name" at 577,-858.49 h60
Signals - L8:
  text ".Layer_Name" at 577,-858.49 h60
Bottom Layer - L10:
  text "MADE IN U.S." at 5075,733 h60
  text "UL94V-0" at 4966,590 h60
  text ".Layer_Name" at 577,-858.49 h60
Gnd-Plane - L9 (plane layer: these items are gaps in the copper):
  text ".Layer_Name" at 577,-858.49 h60
Gnd-Plane - L7 (plane layer: these items are gaps in the copper):
  text ".Layer_Name" at 577,-858.49 h60
Gnd-Plane - L4 (plane layer: these items are gaps in the copper):
  text ".Layer_Name" at 577,-858.49 h60
  text ".Layer_Name" at 577,-858.49 h60
Gnd-Plane - L2 (plane layer: these items are gaps in the copper):
  lines w10: 0,530 406,530 406,642 495,731 607,731 900,438 2353,438 2353,262 2417,198 2558,198 2681,75 3075,75 3165,165 3165,302 3250,387 3250,763 3120,893 2650,893 2650,975 2353,975 2353,577.37 879.26,577.37 643.63,813 438,813 406,845 406,1035 0,1035
  text ".Layer_Name" at 577,-858.49 h60
Pwr Plane - L5 (plane layer: these items are gaps in the copper):
  lines w10: 0,1035 1090,1035 ; 406,1035 406,845 438,813 643.63,813 879.26,577.37 1667.28,577.37 1667.28,376 1767.28,376 1767.28,577.37 2018,577.37 2018,975 2650,975 2650,893 3120,893 3250,763 3250,190 4696,190 4696,0 ; 2785,2680 2785,2081 1115.04,2081 1025,1990.96 1025,1844.89 1090,1779.89 1090,652 1200,652 1200,1035 2009,1035 2009,1245 1440,1245 1440,1675 1405,1710 1405,1885 1435,1915 2427,1915 2452,1940 2871,1940 2871,1990 3204,1990 3204,1040 3388,1040 ; 2971,1990 2971,2680 ; 3388,2680 3388,1040 ; 3473,190 3473,1040 3388,1040 ; 3645,2680 3645,1990 4126,1990 ; 4342,1990 5739,1990 ; 4796,0 4796,565 5544,565 5544,665 5739,665 ; 1655,1558 1715,1558 1715,1513 2280,1513 2378,1415 2862,1415 2862,1376 2941,1376 2941,1463 3093.55,1463 3093.55,1740 3050.55,1740 3050.55,1840 1922,1840 1922,1865 1841,1865 1841,1712.27 1655,1712.27 1655,1558 ; 4126,1040 4126,2419 4342,2419 4342,1184 4554,1184 4554,1040 4126,1040
  text ".Layer_Name" at 577,-858.49 h60

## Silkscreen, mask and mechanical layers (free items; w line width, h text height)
Top Overlay:
  text "ADC12J2700" at 5526,1056 h60 r90
  text "ADC12J1600" at 5672,1055 h60 r90
  text "ADC12JXXXXEVM A" at 5369,511 h60 r90
  text "LM15851" at 5524,190 h60 r90
  text "ADC12J4000" at 5674,190 h60 r90
  text ".Layer_Name" at 577,-858.49 h60
Bottom Overlay:
  rectangle: 4046,1425 4346,1525
  text ".PCB_Rev" at 4489,1441 h60
  text ".PRJ_Number" at 4885,1441 h60
  text "-" at 4414,1430.5 h60
  text ".Layer_Name" at 577,-858.49 h60
Top Paste:
  text ".Layer_Name" at 577,-858.49 h60
Bottom Paste:
  text ".Layer_Name" at 577,-858.49 h60
Top Solder:
  text ".Layer_Name" at 577,-858.49 h60
  text ".Layer_Name" at 577,-858.49 h60
Bottom Solder:
  text ".Layer_Name" at 577,-858.49 h60
Drill Guide:
  text ".Layer_Name" at 577,-858.49 h60
M1 Board Outline:
  the board outline again, w10
  text ".Layer_Name" at 577,-858.49 h60
M2 Board Dimensions:
  rectangle: 124.5,-410.5 499.5,-285.5
  rectangle: -0.5,-285.5 124.5,-160.5
  lines w7: -0.5,-285.5 999.5,-285.5 ; 124.5,-410.5 124.5,-160.5 ; 249.5,-410.5 249.5,-160.5 ; 499.5,-410.5 499.5,-160.5 ; 749.5,-410.5 749.5,-160.5 ; -0.5,-410.5 -0.5,-160.5 999.5,-160.5 999.5,-410.5 -0.5,-410.5
  lines w10: -0.5,-475.5 -0.5,-455.5 ; 59.5,-485.5 -0.5,-465.5 ; 59.5,-445.5 -0.5,-465.5 ; 223.58,-465.5 -0.5,-465.5 ; 775.42,-465.5 999.5,-465.5 ; 939.5,-485.5 999.5,-465.5 ; 939.5,-445.5 999.5,-465.5 ; 999.5,-475.5 999.5,-455.5
  text "1000 (mil)" at 233.58,-501.49 h60
  text ".Layer_Name" at 577,-858.49 h60
M3 3D STEP Top:
  text ".Layer_Name" at 577,-858.49 h60
M4 3D STEP Bottom:
  text ".Layer_Name" at 577,-858.49 h60
M5 Assembly Top:
  lines w7: 6293,-129.5 7418,-129.5 ; 6293,-9.5 7418,-9.5 ; 6293,110.5 7418,110.5 ; 6293,233 7415.5,233 ; 6608,-249.5 6608,353 ; 6293,-249.5 6293,353 7418,353 7418,-249.5 6293,-249.5
  lines w10: -292,-930.17 6308,-930.17 ; -292,-726.83 6310,-726.83 ; -292,-523.5 -292,-1133.5 3713,-1133.5 6310,-1133.5 6310,-523.5 -291.5,-523.5 -291.5,-1133.5 1284,-1133.5 ; 2173,-1133.5 2173,-523.5 ; 3440,-726.83 3440,-523.5 ; 4280,-726.83 4280,-523.5 ; 4902,-1140 4902,-937.17
  text "TABLE 1" at 6680.5,388 h40
  text "Variant" at 6318,278 h40
  text "Label text" at 6753,278 h40
  text "001" at 6385.5,158 h40
  text "LM15851EVM" at 6663,155.5 h40
  text "002" at 6385.5,33 h40
  text "ADC12J4000EVM" at 6658,30.5 h40
  text "003" at 6385.5,-84.5 h40
  text "ADC12J2700EVM" at 6663,-87 h40
  text "004" at 6385.5,-209.5 h40
  text "ADC12J1600EVM" at 6658,-212 h40
  text "COMPONENTS MARKED 'DNP' SHOULD NOT BE POPULATED, AND MAY NOT BE IN BILL OF MATERIALS" at 1153.5,-318.5 h60
  text "ASSEMBLY VARIANT:" at 1153,-434 h60
  text ".VariantName" at 2189,-434 h60
  text "PCB VIEWED FROM TOP SIDE" at -228.5,-655.67 h60
  text "BOARD #:" at 2248,-655.67 h60
  text ".PRJ_Number" at 2793.5,-655.67 h60
  text "REV:" at 3638,-655.67 h60
  text ".PCB_Rev" at 3929.5,-655.67 h60
  text "SVN REV:" at 4476,-655.67 h60
  text ".VersionControl_RevNumber" at 4982,-655.67 h60
  text "IGNORE ->" at -228.5,-858.49 h60
  text "PLOT NAME =" at -228.5,-1064.34 h60
  text ".plot_File_Name" at 577,-1064.34 h60
  text "GENERATED    :" at 2250,-1064.34 h60
  text ".Print_Date" at 3119.5,-1064.34 h60
  text ".Print_Time" at 3848.5,-1064.34 h60
  text "TEXAS INSTRUMENTS" at 5113,-1064.34 h60
M6 Assembly Bottom:
  lines w10: -292.5,-727.33 6309.5,-727.33 ; -290.5,-930.67 6309.5,-930.67 ; 1115.5,-1140.5 1115.5,-937.67 ; 1737.5,-727.33 1737.5,-524 ; 2577.5,-727.33 2577.5,-524 ; 3844.5,-1134 3844.5,-524 ; 4733.5,-1134 6309,-1134 6309,-524 -292.5,-524 -292.5,-1134 2304.5,-1134 6309.5,-1134 6309.5,-524
  text "COMPONENTS MARKED 'DNP' SHOULD NOT BE POPULATED, AND MAY NOT BE IN BILL OF MATERIALS" at 6102,-318 h60
  text ".VariantName" at 5058,-434 h60
  text "ASSEMBLY VARIANT:" at 6097,-434 h60
  text ".VersionControl_RevNumber" at 1035.5,-656.17 h60
  text "SVN REV:" at 1541.5,-656.17 h60
  text ".PCB_Rev" at 2088,-656.17 h60
  text "REV:" at 2379.5,-656.17 h60
  text ".PRJ_Number" at 3224,-656.17 h60
  text "BOARD #:" at 3769.5,-656.17 h60
  text "PCB VIEWED FROM BOTTOM SIDE" at 6246,-656.17 h60
  text "IGNORE ->" at 2547.85,-858.49 h60
  text "TEXAS INSTRUMENTS" at 904.5,-1064.84 h60
  text ".Print_Time" at 2169,-1064.84 h60
  text ".Print_Date" at 2898,-1064.84 h60
  text "GENERATED    :" at 3767.5,-1064.84 h60
  text ".plot_File_Name" at 5440.5,-1064.84 h60
  text "PLOT NAME =" at 6246,-1064.84 h60
M9 Title Sheet:
  drawing of 57 lines, arcs and shapes, not listed
  text "1" at 739.84,8036.5 h70
  text "2" at 3235.5,8036.5 h70
  text "3" at 5724.84,8036.5 h70
  text "4" at 8231.51,8036.5 h70
  text "5" at 10730.5,8036.5 h70
  text "6" at 13235.5,8036.5 h70
  text "A" at -416.5,6893.5 h70
  text "A" at 14383.5,6893.5 h70
  text "B" at -416.5,4513.5 h70
  text "B" at 14383.5,4513.5 h70
  text "C" at -416.5,2138.5 h70
  text "C" at 14383.5,2138.5 h70
  text "PROJECT TITLE:" at 11343.5,277.5 h45
  text ".PRJ_Title" at 11393.5,144.17 h70
  text "DESIGNED FOR:" at 11343.5,-23.5 h45
  text ".PRJ_Customer" at 11393.5,-163.5 h70
  text "D" at -416.5,-231.5 h70
  text "D" at 14383.5,-231.5 h70
  text "FILE NAME:" at 11343.5,-323.5 h45
  text ".PCB_File_Name_No_Path" at 11393.5,-443.5 h70
  text "Texas Instruments (TI) and/or its licensors do not warrant the accuracy or completeness of this specification" at 6374,-605.34 h45
  text "ENGINEER:" at 11343.5,-613.5 h45
  text "LAYOUT BY:" at 12848.5,-613.5 h45
  text "or any information contained therein. TI and/or its licensors do not warrant that this design will meet" at 6329.01,-718 h45
  text ".PRJ_Engineer" at 11393.5,-768.49 h70
  text ".PCB_Layout" at 12899,-768.49 h70
  text "the specifications, will be suitable for your application or fit for any particular purpose, or will operate in" at 6329.01,-830.67 h45
  text ".Layer_Name" at 577,-858.49 h60
  text "ALTIUM DESIGNER VERSION:" at 12848.5,-923.5 h45
  text "an implementation. TI and/or its licensors do not warrant that the design is production worthy. You should" at 6329.01,-943.33 h45
  text "completely validate and test your design implementation to confirm the system functionality for your application." at 6374,-1056 h45
  text ".print_Scale" at 11393.5,-1056.83 h70
  text ".Application_BuildNumber" at 12899,-1056.83 h70
  text "1" at 739.84,-1263.5 h70
  text "2" at 3235.5,-1263.5 h70
  text "3" at 5724.84,-1263.5 h70
  text "4" at 8231.51,-1263.5 h70
  text "5" at 10730.5,-1263.5 h70
  text "6" at 13235.5,-1263.5 h70
M10 Fab Notes:
  drawing of 207 lines, arcs and shapes, not listed
  text "DESIGN INFORMATION" at 12381.02,6810 h60
  text "(REFER ALSO ARRAY/PANEL PROFILING INFORMATION)" at 12019.46,6648.29 h60
  text "BOARD SIZE" at 11333.46,6644 h60
  text "X" at 12301.46,6516.18 h60
  text "Number of Layers :" at 11736.46,6319 h60
  text "10" at 12831.27,6309 h60
  text "MIN. TRACK WIDTH:" at 11736.46,6180 h60
  text "4" at 12832.7,6180 h60
  text "MIL" at 12987.46,6180 h60
  text "MIN. CLEARANCE:" at 11736.46,6048 h60
  text "4" at 12832.7,6048 h60
  text "MIL" at 12987.46,6048 h60
  text "MIN. VIA PAD SIZE:" at 11736.46,5916 h60
  text "18" at 12802.71,5916 h60
  text "MIL" at 12987.46,5916 h60
  text "0.05mm (2MIL)" at 12431.46,5774.29 h60
  text "MINIMUM ANNULAR RING" at 11407.23,5770 h60
  text "EXTERNAL" at 13139.46,5770 h60
  text "PER" at 11607.23,5652 h60
  text "IPC-D-275 CLASS 2 LEVEL C" at 11827.23,5652 h60
  text "MIL, HOLES" at 13315.46,5539.71 h60
  text "+/-" at 12923,5539 h60
  text "+/-" at 13777,5539 h60
  text "REGISTRATION TOLERANCES:" at 11407.23,5534 h60
  text "METAL" at 12607,5534 h60
  text "5" at 13183.2,5534 h60
  text "3" at 14016.2,5534 h60
  text "MIL" at 14132.46,5534 h60
  text "MATERIAL:" at 11332.46,5324.54 h60
  text "FR-4 High Tg" at 12318.9,5184.21 h60
  text "FR-4" at 11793.46,5175.64 h60
  text "X" at 13054.46,5176 h60
  text "OTHER SEE LAYER STACK UP" at 13241.46,5175.64 h50
  text "62 MIL (1.6mm) +/-10%" at 12073.56,5012.92 h60
  text "THICKNESS:" at 11407.23,5008.64 h60
  text "X" at 11945.4,5008.64 h60
  text "OTHER" at 13358.46,5008.64 h60
  text "TOLERANCE:" at 11407.23,4850.64 h60
  text "X" at 12246.53,4850.64 h60
  text "ANSI IPC-6012 TYPE 3 CLASS 2" at 12433.48,4850.64 h60
  text "OTHER +/-" at 12433.46,4694.64 h60
  text "BOW & TWIST:" at 11407.23,4537.64 h60
  text "X" at 12246.53,4537.64 h60
  text "ANSI IPC-6012 TYPE 3 CLASS 2" at 12433.48,4537.64 h60
  text "OTHER +/-" at 12433.46,4379.13 h60
  text "COPPER THICKNESS (FINISHED):" at 11332.46,4243.64 h60
  text "SEE 001svengprerelstackup18.pdf FOR CORRECT IMPEDANCE INFORMATION" at 5000,4175 h100
  text "0.7MIL (0.5oz)" at 12212.46,4090.92 h60
  text "1.4MIL (1oz)" at 12979.46,4090.92 h60
  text "2.8MIL (2oz)" at 13706.46,4090.92 h60
  text "OUTER:" at 11689.46,4086.64 h60
  text "X" at 12084,4086 h60
  text "0.7MIL (0.5oz)" at 12212.46,3933.92 h60
  text "2.8MIL (2oz)" at 12979.46,3933.92 h60
  text "N/A" at 13706,3934.29 h60
  text "INNER SIGNAL:" at 11400.38,3929.64 h60
  text "X" at 12085.42,3929.64 h60
  text "X" at 12852.42,3929.64 h60
  text "Single ended tracks 50 ohms Top & Bottom Layers equal 8.0mil width." at 5000,3900 h100
  text "DRILLING:" at 11332.46,3790.64 h60
  text "REFERENCE:" at 11407.23,3673.64 h60
  text "X" at 12055.46,3673.64 h60
  text "AS SHOWN" at 12242.46,3673.64 h60
  text "X" at 12956.46,3673.64 h60
  text "NC_DRILL FILES" at 13093.46,3673.64 h60
  text "Differential tracks 100 ohms Top & Bottom Layers equal 8.0mil width & 8.0mil spacing." at 5000,3625 h100
  text "PTH MIN COPPER THICKNESS:" at 11407.23,3515.64 h60
  text "X" at 12757.46,3515.64 h60
  text "1MIL" at 12894.46,3515.64 h60
  text "OTHER" at 13391.46,3515.64 h60
  text "BOARD FINISH:" at 11332.46,3356.64 h60
  text "Differential tracks 100 ohms Inner Layers equal 4.0mil width & 4.0mil spacing." at 5000,3350 h100
  text "SILKSCREEN:" at 11487.68,3238.64 h60
  text "X" at 12436.46,3238.64 h60
  text "TOP" at 12562.46,3238.64 h60
  text "X" at 12946.46,3238.64 h60
  text "BOTTOM" at 13073.46,3238.64 h60
  text "Back Drill high speed lines 8.001 mil vias from Layer 1 to Layer 7, leaving the via" at 5000,3075 h100
  text "SILKSCREEN COLOR:" at 11487.68,3071.64 h60
  text "X" at 12435.42,3071.64 h60
  text "WHITE" at 12562.46,3071.64 h60
  text "OTHER" at 13073.46,3071.64 h60
  text "SOLDER RESIST COLOR:" at 11487.68,2901.64 h60
  text "connecting layer 8 to layer 10." at 5000,2800 h100
  text "X" at 12055.42,2742.44 h60
  text "GREEN" at 12182.46,2742.44 h60
  text "BLUE" at 12773.46,2742.44 h60
  text "OTHER" at 13311.46,2742.44 h60
  text "IMMERSION GOLD (ENIG)" at 12393.46,2553.92 h60
  text "SURFACE FINISH:" at 11332.46,2549.64 h60
  text "X" at 12206.51,2549.64 h60
  text "IMM. TIN/SILVER OR EQUIV" at 11662,2392.64 h60
  text "OTHER" at 13093.46,2392.64 h60
  text "ARRAY/PANEL:" at 11332.46,2213.64 h60
  text "CUT AND TRIM PER MECH LAYER 1" at 12393.46,2209.35 h60
  text "N.C. ROUTE" at 12393.46,2057.64 h60
  text "X" at 13072.46,2057.64 h60
  text "V. SCORE" at 13259.46,2057.64 h60
  text "CERTIFICATION:" at 11332.46,1920.64 h60
  text "MATERIALS AND WORKMANSHIP FOR ALL PCBS" at 12057.46,1920.64 h60
  text "TO MEET OR EXCEED THE REQUIREMENTS OF:" at 12057.46,1822.64 h60
  text "X" at 11683.96,1686.13 h60
  text "ANSI IPC-A-600F CLASS ->" at 11822.96,1686.13 h60
  text "X" at 13462.02,1686.13 h60
  text "2" at 13580.96,1686.14 h60
  text "1" at 13265.96,1684.64 h60
  text "3" at 13934.96,1684.64 h60
  text "X" at 11686.02,1526.64 h60
  text "UL 94V-0" at 11822.96,1526.64 h60
  text "X" at 12498.02,1526.64 h60
  text "RoHS" at 12634.96,1526.64 h60
  text "OTHER" at 13279.36,1526.64 h60
  text "PER ORDER" at 13676.42,1526.64 h60
  text "ADDITIONAL REQUIREMENTS:" at 11332.46,1385.64 h60
  text "MICROSECTION:" at 11407.23,1270.64 h60
  text "YES" at 12312.96,1270.64 h60
  text "REQUIRED" at 13174.46,1114.49 h60
  text "BARE BOARD ELEC. TEST:" at 11407.23,1111.64 h60
  text "NONE" at 12712.96,1111.64 h60
  text "X" at 13047.46,1111.64 h60
  text "PER ORDER" at 13766.46,1111.64 h60
  text "MANUFACTURER'S ID/LOGO:" at 11407.23,954.64 h60
  text "RAIL" at 12872.96,950.35 h60
  text "X" at 13247.46,950.35 h60
  text "METAL" at 13364.77,950.35 h60
  text "SILK" at 13876.46,950.35 h60
  text ".Layer_Name" at 577,-858.49 h60
M11 Gerber Information:
  lines w10: -292,-930.17 6308,-930.17 ; -292,-726.83 6310,-726.83 ; -292,-523.5 -292,-1133.5 3713,-1133.5 6310,-1133.5 6310,-523.5 -291.5,-523.5 -291.5,-1133.5 1284,-1133.5 ; 2173,-1133.5 2173,-523.5 ; 3440,-726.83 3440,-523.5 ; 4280,-726.83 4280,-523.5 ; 4902,-1140 4902,-937.17
  text "ALL ARTWORK VIEWED FROM TOP SIDE" at -228.5,-655.67 h60
  text "BOARD #:" at 2248,-655.67 h60
  text ".PRJ_Number" at 2793.5,-655.67 h60
  text "REV:" at 3638,-655.67 h60
  text ".PCB_Rev" at 3929.5,-655.67 h60
  text "SVN REV:" at 4476,-655.67 h60
  text ".VersionControl_RevNumber" at 4982,-655.67 h60
  text "LAYER NAME =" at -228.5,-858.49 h60
  text "PLOT NAME =" at -228.5,-1064.34 h60
  text ".plot_File_Name" at 577,-1064.34 h60
  text "GENERATED    :" at 2250,-1064.34 h60
  text ".Print_Date" at 3119.5,-1064.34 h60
  text ".Print_Time" at 3848.5,-1064.34 h60
  text "TEXAS INSTRUMENTS" at 5113,-1064.34 h60
M12 Stackup:
  lines w11: 4912,4388 4125,6075 4912,7762
  lines w12: 5018.02,7259.85 11193.98,7259.85 ; 5018.02,7472.75 11193.98,7472.75 ; 4955,4449 ccw(c5024,4449) 5024,4380 11188,4380 ccw(c11188,4449) 11257,4449 11257,7692 ccw(c11188,7692) 11188,7761 5024,7761 ccw(c5024,7692) 4955,7692 4955,4449
  text "Layer Stack Up Detail for: SV600847A1.PcbDoc" at 5018.02,7534.88 h110
  text "Layer" at 5018.02,7393.25 h49
  text "Gerber" at 6358.46,7393.25 h49
  text "Copper" at 7016.09,7393.25 h49
  text "Dielectric" at 7753.73,7393.25 h49
  text "Dielectric" at 8525.66,7393.25 h49
  text "Dielectric" at 9509.72,7393.25 h49
  text "Dielectric" at 10281.65,7393.25 h49
  text "Name" at 5018.02,7295.25 h49
  text "Document" at 6358.46,7295.25 h49
  text "Thickness" at 7016.09,7295.25 h49
  text "Height" at 7753.73,7295.25 h49
  text "Material" at 8525.66,7295.25 h49
  text "Constant" at 9509.72,7295.25 h49
  text "Type" at 10281.65,7295.25 h49
  text "Top Solder Mask" at 5018.02,7142.44 h69
  text "(.GTS)" at 6358.46,7142.44 h69
  text "0.4mil" at 7753.73,7142.44 h69
  text "Solder Resist" at 8525.66,7142.44 h69
  text "3.50" at 9509.72,7142.44 h69
  text "Top Layer L1" at 5018.02,6919.62 h69
  text "(.GTL)" at 6358.46,6919.62 h69
  text "0.6mil" at 7016.09,6919.62 h69
  text "4mil" at 7753.73,6808.21 h69
  text "Rogers RO4350" at 8525.66,6808.21 h69
  text "3.66" at 9509.72,6808.21 h69
  text "Core" at 10281.65,6808.21 h69
  text "Gnd-Plane - L2" at 5018.02,6696.8 h69
  text "(.GP1)" at 6358.46,6696.8 h69
  text "1.2mil" at 7016.09,6696.8 h69
  text "6.7mil" at 7753.73,6585.39 h69
  text "NP 4000-6" at 8525.66,6585.39 h69
  text "4.11" at 9509.72,6585.39 h69
  text "PrePreg" at 10281.65,6585.39 h69
  text "Signals - L3" at 5018.02,6473.98 h69
  text "(.G1)" at 6358.46,6473.98 h69
  text "0.6mil" at 7016.09,6473.98 h69
  text "6mil" at 7753.73,6362.57 h69
  text "NP 4000-6" at 8525.66,6362.57 h69
  text "4.11" at 9509.72,6362.57 h69
  text "Core" at 10281.65,6362.57 h69
  text "Gnd-Plane - L4" at 5018.02,6251.16 h69
  text "(.GP2)" at 6358.46,6251.16 h69
  text "1.2mil" at 7016.09,6251.16 h69
  text "4.1mil" at 7753.73,6139.75 h69
  text "NP 4000-6" at 8525.66,6139.75 h69
  text "4.11" at 9509.72,6139.75 h69
  text "PrePreg" at 10281.65,6139.75 h69
  text "SEE 001svengprerelstackup18.pdf FOR CORRECT STACKUP INFORMATION" at -46,6041 h66
  text "Pwr Plane - L5" at 5018.02,6028.34 h69
  text "(.GP3)" at 6358.46,6028.34 h69
  text "1.2mil" at 7016.09,6028.34 h69
  text "6mil" at 7753.73,5916.93 h69
  text "NP 4000-6" at 8525.66,5916.93 h69
  text "4.11" at 9509.72,5916.93 h69
  text "Core" at 10281.65,5916.93 h69
  text "Signals - L6" at 5018.02,5805.51 h69
  text "(.G2)" at 6358.46,5805.51 h69
  text "0.6mil" at 7016.09,5805.51 h69
  text "6.7mil" at 7753.73,5694.1 h69
  text "NP 4000-6" at 8525.66,5694.1 h69
  text "4.11" at 9509.72,5694.1 h69
  text "PrePreg" at 10281.65,5694.1 h69
  text "Gnd-Plane - L7" at 5018.02,5582.69 h69
  text "(.GP4)" at 6358.46,5582.69 h69
  text "1.2mil" at 7016.09,5582.69 h69
  text "4mil" at 7753.73,5471.28 h69
  text "Rogers RO4350" at 8525.66,5471.28 h69
  text "3.66" at 9509.72,5471.28 h69
  text "Core" at 10281.65,5471.28 h69
  text "Signals - L8" at 5018.02,5359.87 h69
  text "(.G3)" at 6358.46,5359.87 h69
  text "0.6mil" at 7016.09,5359.87 h69
  text "7.3mil" at 7753.73,5248.46 h69
  text "Rogers RO4350" at 8525.66,5248.46 h69
  text "3.66" at 9509.72,5248.46 h69
  text "PrePreg" at 10281.65,5248.46 h69
  text "Gnd-Plane - L9" at 5018.02,5137.05 h69
  text "(.GP5)" at 6358.46,5137.05 h69
  text "1.2mil" at 7016.09,5137.05 h69
  text "4mil" at 7753.73,5025.64 h69
  text "Rogers RO4350" at 8525.66,5025.64 h69
  text "3.66" at 9509.72,5025.64 h69
  text "Core" at 10281.65,5025.64 h69
  text "Bottom Layer - L10" at 5018.02,4914.23 h69
  text "(.GBL)" at 6358.46,4914.23 h69
  text "0.6mil" at 7016.09,4914.23 h69
  text "Bottom Solder Mask" at 5018.02,4691.41 h69
  text "(.GBS)" at 6358.46,4691.41 h69
  text "0.4mil" at 7753.73,4691.41 h69
  text "Solder Resist" at 8525.66,4691.41 h69
  text "3.50" at 9509.72,4691.41 h69
  text ".Layer_Name" at 577,-858.49 h60
M13 Component Bodies Top:
  text ".Layer_Name" at 577,-858.49 h60
M14 Component Bodies Bottom:
  text ".Layer_Name" at 577,-858.49 h60
M15 Courtyards Top:
  text ".Layer_Name" at 577,-858.49 h60
M16 Courtyards Bottom:
  text ".Layer_Name" at 577,-858.49 h60
Drill Drawing:
  text ".legend" at 6076.5,725.5 h60
  text "Drill Table" at 6101.5,540.5 h60
  text ".Layer_Name" at 577,-858.49 h60

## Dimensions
0,0 to 5739,0 on M2 Board Dimensions
0,0 to 0,2680 on M2 Board Dimensions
